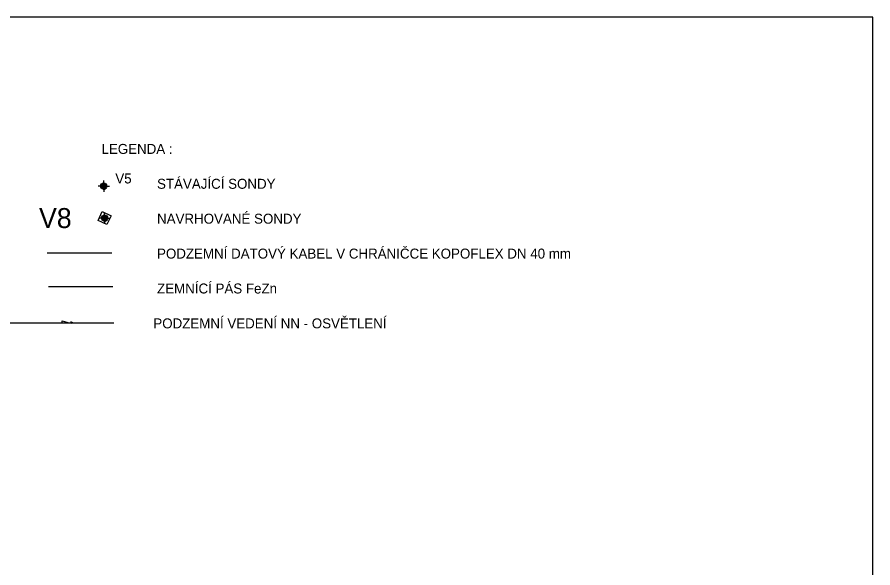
# Model space of a CAD drawing. Extents: x -517788 to -517166, y -1177087 to -1176790.
# Drawn here: x -517251.8 to -517165.9, y -1176845.5 to -1176790.2 of the extents above; entities that cross this region are included whole.
import ezdxf

# ---------------------------------------------------------------- set-up
doc = ezdxf.new("R2010")
doc.units = 0
doc.layers.add('mapove znacky', color=7, linetype='Continuous')
doc.layers.add('označení lomového bodu', color=7, linetype='Continuous')

msp = doc.modelspace()

# ---------------------------------------------------------------- linework, layer by layer
at = {"layer": 'mapove znacky'}
for p, q in [((-517243.399, -1176807.172), (-517243.649, -1176807.172)), ((-517243.397, -1176807.211), (-517242.898, -1176806.923)), ((-517243.396, -1176807.13), (-517242.969, -1176806.883)), ((-517243.379, -1176807.282), (-517242.846, -1176806.974)), ((-517243.365, -1176807.031), (-517243.07, -1176806.861)), ((-517243.347, -1176807.344), (-517242.808, -1176807.033)), ((-517243.302, -1176807.399), (-517242.783, -1176807.099)), ((-517243.241, -1176807.444), (-517242.774, -1176807.175)), ((-517243.157, -1176807.477), (-517242.788, -1176807.264)), ((-517243.087, -1176806.86), (-517243.087, -1176806.61)), ((-517242.774, -1176807.172), (-517242.524, -1176807.172)), ((-517243.087, -1176807.485), (-517243.087, -1176807.735)), ((-517243.017, -1176807.477), (-517242.858, -1176807.385)), ((-517243.003, -1176810.066), (-517243.003, -1176809.816)), ((-517243.315, -1176810.379), (-517243.565, -1176810.379)), ((-517243.313, -1176810.417), (-517242.814, -1176810.13)), ((-517243.312, -1176810.336), (-517242.885, -1176810.09)), ((-517243.295, -1176810.488), (-517242.762, -1176810.18)), ((-517243.281, -1176810.238), (-517242.986, -1176810.067)), ((-517243.263, -1176810.551), (-517242.724, -1176810.239)), ((-517243.218, -1176810.605), (-517242.699, -1176810.306)), ((-517243.157, -1176810.651), (-517242.69, -1176810.382)), ((-517243.073, -1176810.683), (-517242.704, -1176810.47)), ((-517243.003, -1176810.691), (-517243.003, -1176810.941)), ((-517242.933, -1176810.683), (-517242.774, -1176810.592)), ((-517242.69, -1176810.379), (-517242.44, -1176810.379))]:
    msp.add_line(p, q, dxfattribs=at)
for centre in [(-517243.087, -1176807.172), (-517243.003, -1176810.379)]:
    msp.add_circle(centre, 0.312, dxfattribs=at)
at = {"layer": 'označení lomového bodu'}
for p, q in [((-517165.912, -1176790.222), (-517375.912, -1176790.222)), ((-517165.912, -1176938.722), (-517165.912, -1176790.222)), ((-517242.277, -1176813.893), (-517248.75, -1176813.893)), ((-517242.174, -1176817.26), (-517248.647, -1176817.26)), ((-517252.874, -1176820.88), (-517242.088, -1176820.88)), ((-517247.253, -1176820.88), (-517247.253, -1176820.691)), ((-517247.253, -1176820.691), (-517246.565, -1176820.88)), ((-517246.203, -1176820.88), (-517246.378, -1176820.796)), ((-517246.203, -1176820.88), (-517246.378, -1176820.964))]:
    msp.add_line(p, q, dxfattribs=at)
msp.add_lwpolyline([(-517242.777, -1176811.036), (-517243.658, -1176810.613), (-517243.229, -1176809.721), (-517242.348, -1176810.144)], close=True, dxfattribs=at)
for points in [[(-517248.647, -1176820.88), (-517248.646, -1176820.88)], [(-517248.121, -1176820.88), (-517247.253, -1176820.88)], [(-517246.565, -1176820.88), (-517246.203, -1176820.88)], [(-517245.937, -1176820.88), (-517245.153, -1176820.88)], [(-517244.67, -1176820.88), (-517243.76, -1176820.88)], [(-517243.235, -1176820.88), (-517242.318, -1176820.88)]]:
    msp.add_lwpolyline(points, dxfattribs=at)

# ---------------------------------------------------------------- texts
for s, height, p in [('LEGENDA :', 1, (-517243.312, -1176803.943)), ('V5', 1, (-517241.925, -1176806.906)), ('               STÁVAJÍCÍ SONDY', 1, (-517243.312, -1176807.443)), ('V8', 2, (-517249.58, -1176811.378)), ('               NAVRHOVANÉ SONDY', 1, (-517243.312, -1176810.943)), ('               PODZEMNÍ DATOVÝ KABEL V CHRÁNIČCE KOPOFLEX DN 40 mm  ', 1, (-517243.312, -1176814.443)), ('               ZEMNÍCÍ PÁS FeZn      ', 1, (-517243.312, -1176817.943)), ('              PODZEMNÍ VEDENÍ NN - OSVĚTLENÍ', 1, (-517243.312, -1176821.443))]:
    msp.add_text(s, height=height, rotation=360, dxfattribs=at).set_placement(p)

doc.saveas('drawing.dxf')
